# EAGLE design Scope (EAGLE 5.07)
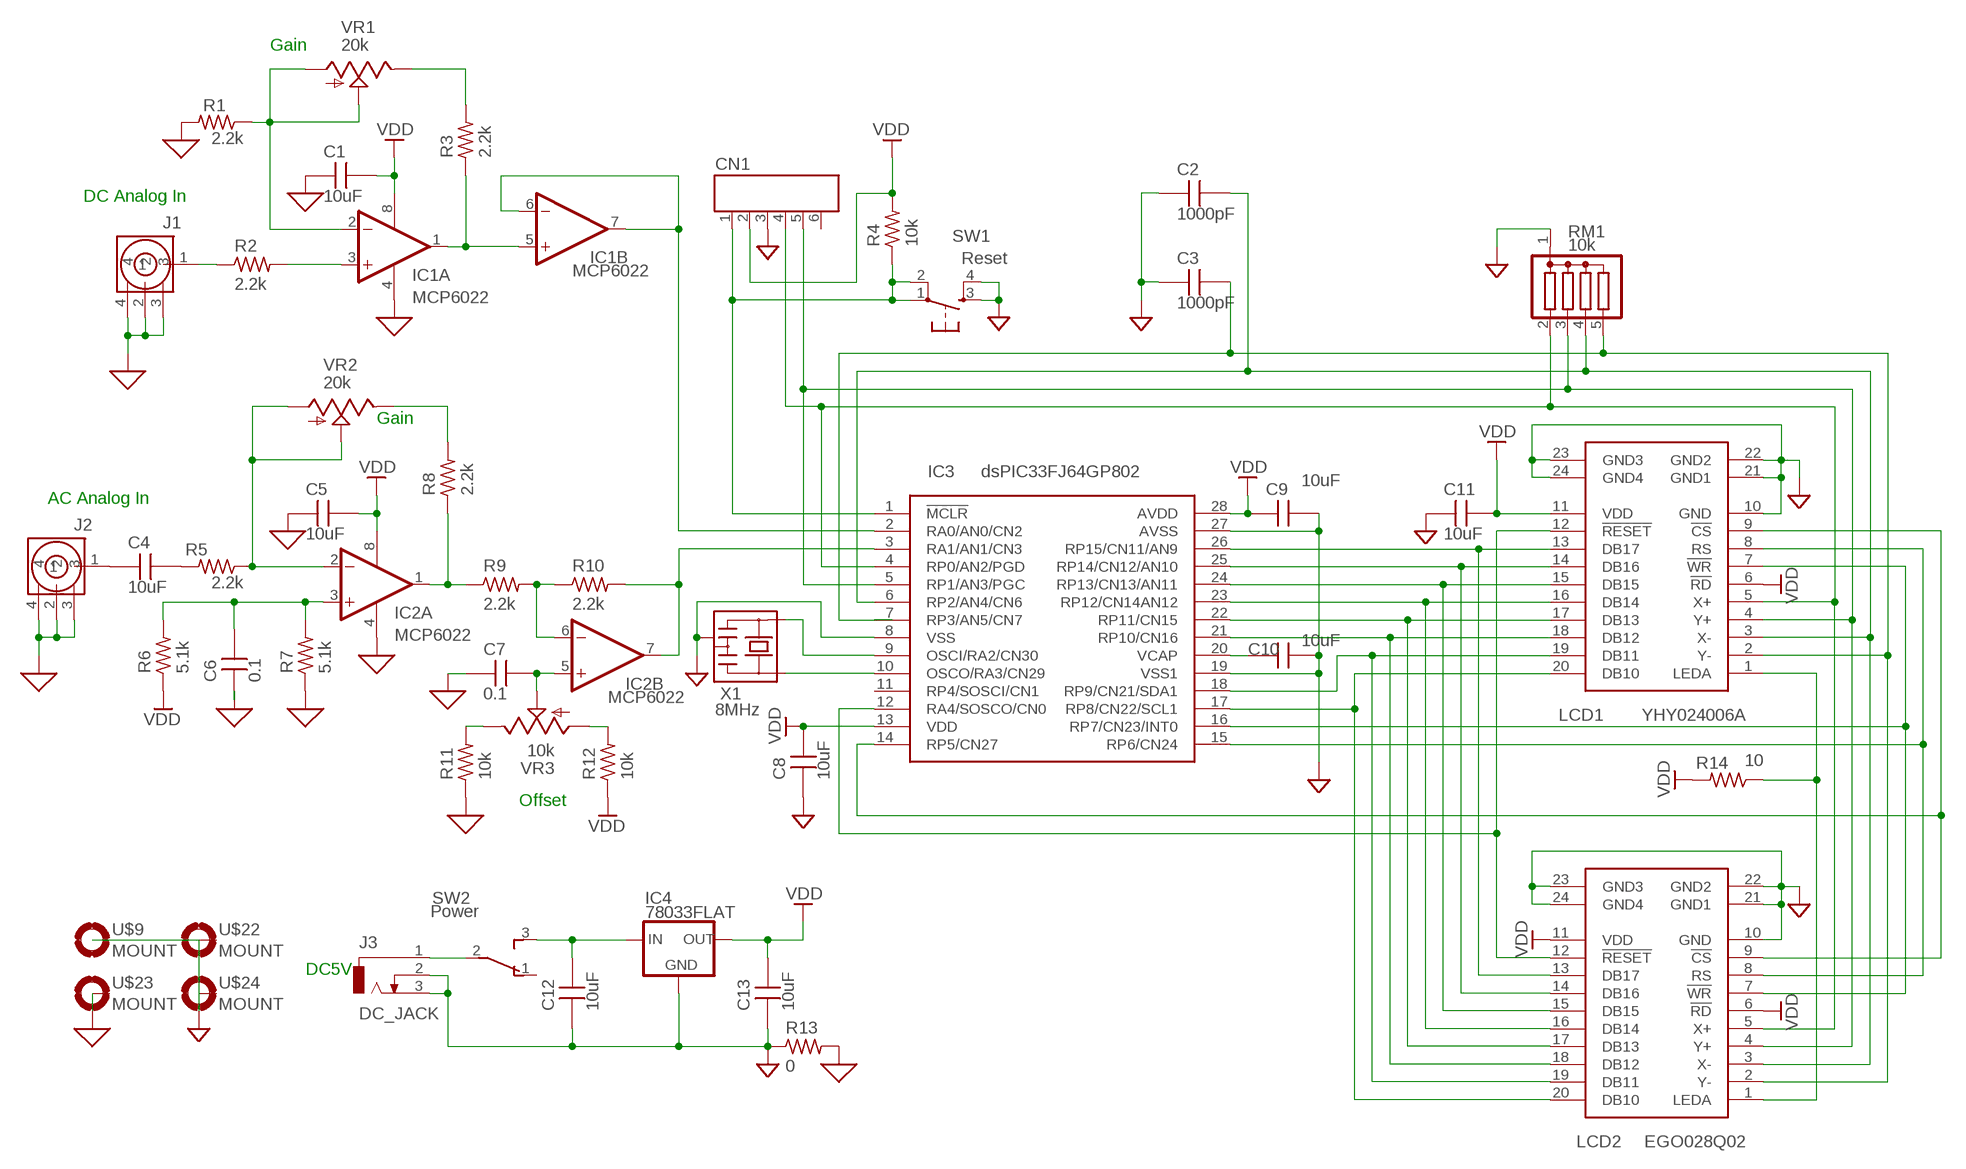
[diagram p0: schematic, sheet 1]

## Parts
C1  10uF  CAPSM3216  [C3216]
C2  1000pF  CAPDIP_2  [CAP_DIP_2]
C3  1000pF  CAPDIP_2  [CAP_DIP_2]
C4  10uF  CAPSM3216  [C3216]
C5  10uF  CAPSM3216  [C3216]
C6  0.1  CAPDIP_2  [CAP_DIP_2]
C7  0.1  CAPDIP_2  [CAP_DIP_2]
C8  10uF  CAPSM3216  [C3216]
C9  10uF  CAPSM3216  [C3216]
C10  10uF  CAPSM3216  [C3216]
C11  10uF  CAPSM3216  [C3216]
C12  10uF  CAPSM3225  [C3225]
C13  10uF  CAPSM3225  [C3225]
CN1  CON_6P  [CON_HRS_DIP_6]
IC1  MCP6022  LM358N  [DIL08]
IC2  MCP6022  LM358N  [DIL08]
IC3  dsPIC33FJ64GP802  DSPIC33FJ64GP802  [DIL28-3]
IC4  78033FLAT  7803FLAT  [TO252]
J1  RCA_JACK  [RCA_JACK]
J2  RCA_JACK  [RCA_JACK]
J3  DC_JACK  [DCJ0202]
LCD1  YHY024006A  LCD_YHY024006ABRD  [LCD_YHY024006ABRD]
LCD2  EGO028Q02  LCD_EGO028Q02BRD  [LCD_EGO028Q02BRD]
R1  2.2k  R0.125W_2P  [R_0.125W_2]
R2  2.2k  R0.125W_2P  [R_0.125W_2]
R3  2.2k  R0.125W_2P  [R_0.125W_2]
R4  10k  R0.125W_2P  [R_0.125W_2]
R5  2.2k  R0.125W_2P  [R_0.125W_2]
R6  5.1k  R0.125W_2P  [R_0.125W_2]
R7  5.1k  R0.125W_2P  [R_0.125W_2]
R8  2.2k  R0.125W_2P  [R_0.125W_2]
R9  2.2k  R0.125W_2P  [R_0.125W_2]
R10  2.2k  R0.125W_2P  [R_0.125W_2]
R11  10k  R0.125W_2P  [R_0.125W_2]
R12  10k  R0.125W_2P  [R_0.125W_2]
R13  0  R0.125W_2P  [R_0.125W_2]
R14  10  R0.125W_2P  [R_0.125W_2]
RM1  10k  RM4  [SIL5]
SW1  Reset  TACT-SW  [B3F-10X]
SW2  Power  SLIDESW-3  [DS-3]
U$9  MOUNT  MOUNT-PAD2.1  [PAD-2.1]
U$22  MOUNT  MOUNT-PAD2.1  [PAD-2.1]
U$23  MOUNT  MOUNT-PAD2.1  [PAD-2.1]
U$24  MOUNT  MOUNT-PAD2.1  [PAD-2.1]
VR1  20k  POTSMALL  [POT_B25P]
VR2  20k  POTSMALL  [POT_B25P]
VR3  10k  POTSMALL  [POT_B25P]
X1  8MHz  CERALOCK  [CSTLS]

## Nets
AGND: C1.1 C5.1 C6.1 C7.1 IC1.4(P:V-) IC2.4(P:V-) J1.2 J1.3 J1.4 J2.2 J2.3 J2.4 R1.2 R7.1 R11.1 R13.2 U$23.B2,1(MOUNT)
GND: C2.1 C3.1 C8.1 C9.2 C10.2 C11.1 C12.1 C13.1 CN1.3 IC3.8(VSS) IC3.19(VSS1) IC3.27(AVSS) IC4.3(GND) J3.2 J3.3 LCD1.10(GND) LCD1.21(GND1) LCD1.22(GND2) LCD1.23(GND3) LCD1.24(GND4) LCD2.10(GND) LCD2.21(GND1) LCD2.22(GND2) LCD2.23(GND3) LCD2.24(GND4) R13.1 RM1.1 SW1.3(S) SW1.4(S1) U$9.B2,1(MOUNT) U$22.B2,1(MOUNT) U$24.B2,1(MOUNT) X1.2
N$1: IC3.26(RP15/CN11/AN9) LCD1.13(DB17) LCD2.13(DB17)
N$2: IC3.25(RP14/CN12/AN10) LCD1.14(DB16) LCD2.14(DB16)
N$3: IC3.24(RP13/CN13/AN11) LCD1.15(DB15) LCD2.15(DB15)
N$4: IC3.23(RP12/CN14AN12) LCD1.16(DB14) LCD2.16(DB14)
N$5: IC3.22(RP11/CN15) LCD1.17(DB13) LCD2.17(DB13)
N$6: IC3.21(RP10/CN16) LCD1.18(DB12) LCD2.18(DB12)
N$7: IC3.18(RP9/CN21/SDA1) LCD1.19(DB11) LCD2.19(DB11)
N$9: IC3.16(RP7/CN23/INT0) LCD1.7(!WR) LCD2.7(!WR)
N$10: C2.2 IC3.6(RP2/AN4/CN6) LCD1.3(X-) LCD2.3(X-) RM1.4
N$11: IC3.14(RP5/CN27) LCD1.9(!CS) LCD2.9(!CS)
N$12: IC3.15(RP6/CN24) LCD1.8(RS) LCD2.8(RS)
N$13: LCD1.1(LEDA) LCD2.1(LEDA) R14.1
N$14: CN1.1 IC3.1(!MCLR) R4.1 SW1.1(P) SW1.2(P1)
N$15: IC3.12(RA4/SOSCO/CN0) LCD1.12(!RESET) LCD2.12(!RESET)
N$16: IC1.3(A:+IN) R2.2
N$17: IC1.6(B:-IN) IC1.7(B:OUT) IC3.2(RA0/AN0/CN2)
N$18: J3.1 SW2.2(P)
N$19: J1.1 R2.1
N$21: IC1.2(A:-IN) R1.1 VR1.A VR1.S
N$22: IC1.1(A:OUT) IC1.5(B:+IN) R3.1
N$23: CN1.4 IC3.4(RP0/AN2/PGD) LCD1.5(X+) LCD2.5(X+) RM1.2
N$24: C10.1 IC3.20(VCAP)
N$25: IC3.9(OSCI/RA2/CN30) X1.3
N$26: C4.1 J2.1
N$27: C3.2 IC3.7(RP3/AN5/CN7) LCD1.2(Y-) LCD2.2(Y-) RM1.5
N$28: C4.2 R5.2
N$29: C12.2 IC4.1(IN) SW2.3(S)
N$30: IC3.17(RP8/CN22/SCL1) LCD1.20(DB10) LCD2.20(DB10)
N$31: R11.2 VR3.E
N$32: R3.2 VR1.E
N$33: R12.2 VR3.A
N$34: IC2.2(A:-IN) R5.1 VR2.A VR2.S
N$35: C6.2 IC2.3(A:+IN) R6.2 R7.2
N$36: IC2.1(A:OUT) R8.1 R9.1
N$37: IC2.6(B:-IN) R9.2 R10.1
N$38: C7.2 IC2.5(B:+IN) VR3.S
N$39: CN1.5 IC3.5(RP1/AN3/PGC) LCD1.4(Y+) LCD2.4(Y+) RM1.3
N$40: R8.2 VR2.E
N$43: IC2.7(B:OUT) IC3.3(RA1/AN1/CN3) R10.2
N$46: IC3.10(OSCO/RA3/CN29) X1.1
VDD: C1.2 C5.2 C8.2 C9.1 C11.2 C13.2 CN1.2 IC1.8(P:V+) IC2.8(P:V+) IC3.13(VDD) IC3.28(AVDD) IC4.2(OUT) LCD1.6(!RD) LCD1.11(VDD) LCD2.6(!RD) LCD2.11(VDD) R4.2 R6.1 R12.1 R14.2
Unconnected: CN1.6 IC3.11(RP4/SOSCI/CN1) SW2.1(O)

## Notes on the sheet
- Gain
- DC Analog In
- Gain
- AC Analog In
- Offset
- DC5V

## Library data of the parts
C1-C13 = MyLib:CAP: Non polar capacitor
CN1 = MyLib:CON_6P: 6P Molex Connector
IC1 IC2 = linear:LM358: OP AMP also LM158; LM258; LM2904 Source: http://cache.national.com/ds/LM/LM158.pdf
IC3 = microchip-dspic:DSPIC33FJ64GP802: dsPIC33 RAM16K CAN
IC4 = MyLib:78*
J1 J2 = MyLib:RCA_JACK
J3 = MyLib:DC_JACK: DC Jack with Switch
LCD1 = MyLib:LCD_YHY024006ABRD: 2.4" TFT Color LCD with Touch Screen Board
LCD2 = MyLib:LCD_EGO028Q02BRD: 2.8" Color LCD Board with Touch Sensor
R1-R14 = MyLib:R: General Resiter 1/8W 1/4W 1/2W V/H
RM1 = MyLib:RM4: 4 Element Register Array Module
SW1 = MyLib:TACT-SW: Tacticle Push Switch
SW2 = MyLib:SLIDESW-3: 3P Slide Switch
U$9 U$22-U$24 = MyLib:MOUNT-PAD: 2.1mm Mount Pad (Connectable to GND)
VR1-VR3 = MyLib:POT: Volume Trimmer Resister
X1 = MyLib:CERALOCK: Ceralock Oscillator

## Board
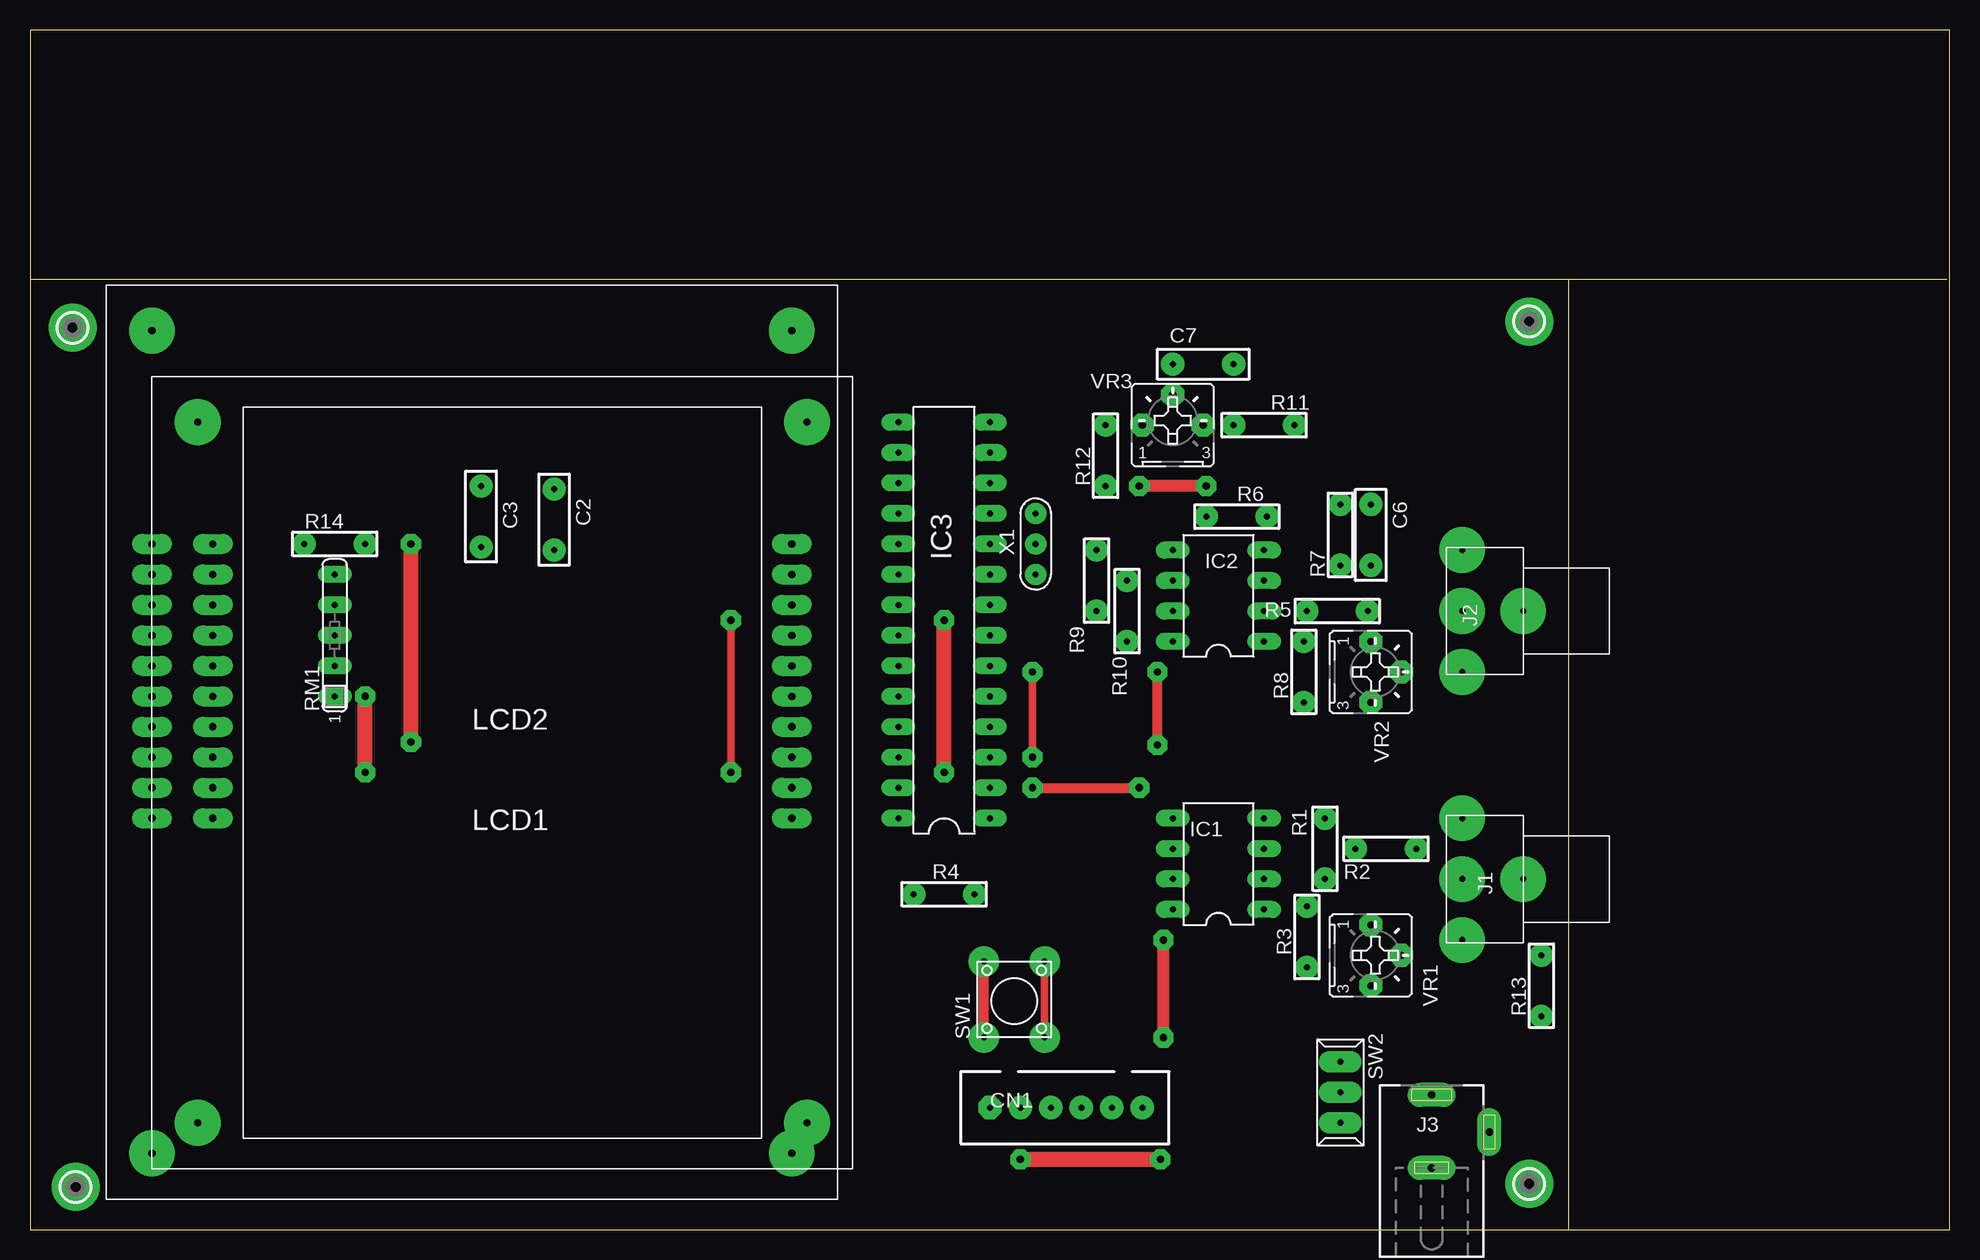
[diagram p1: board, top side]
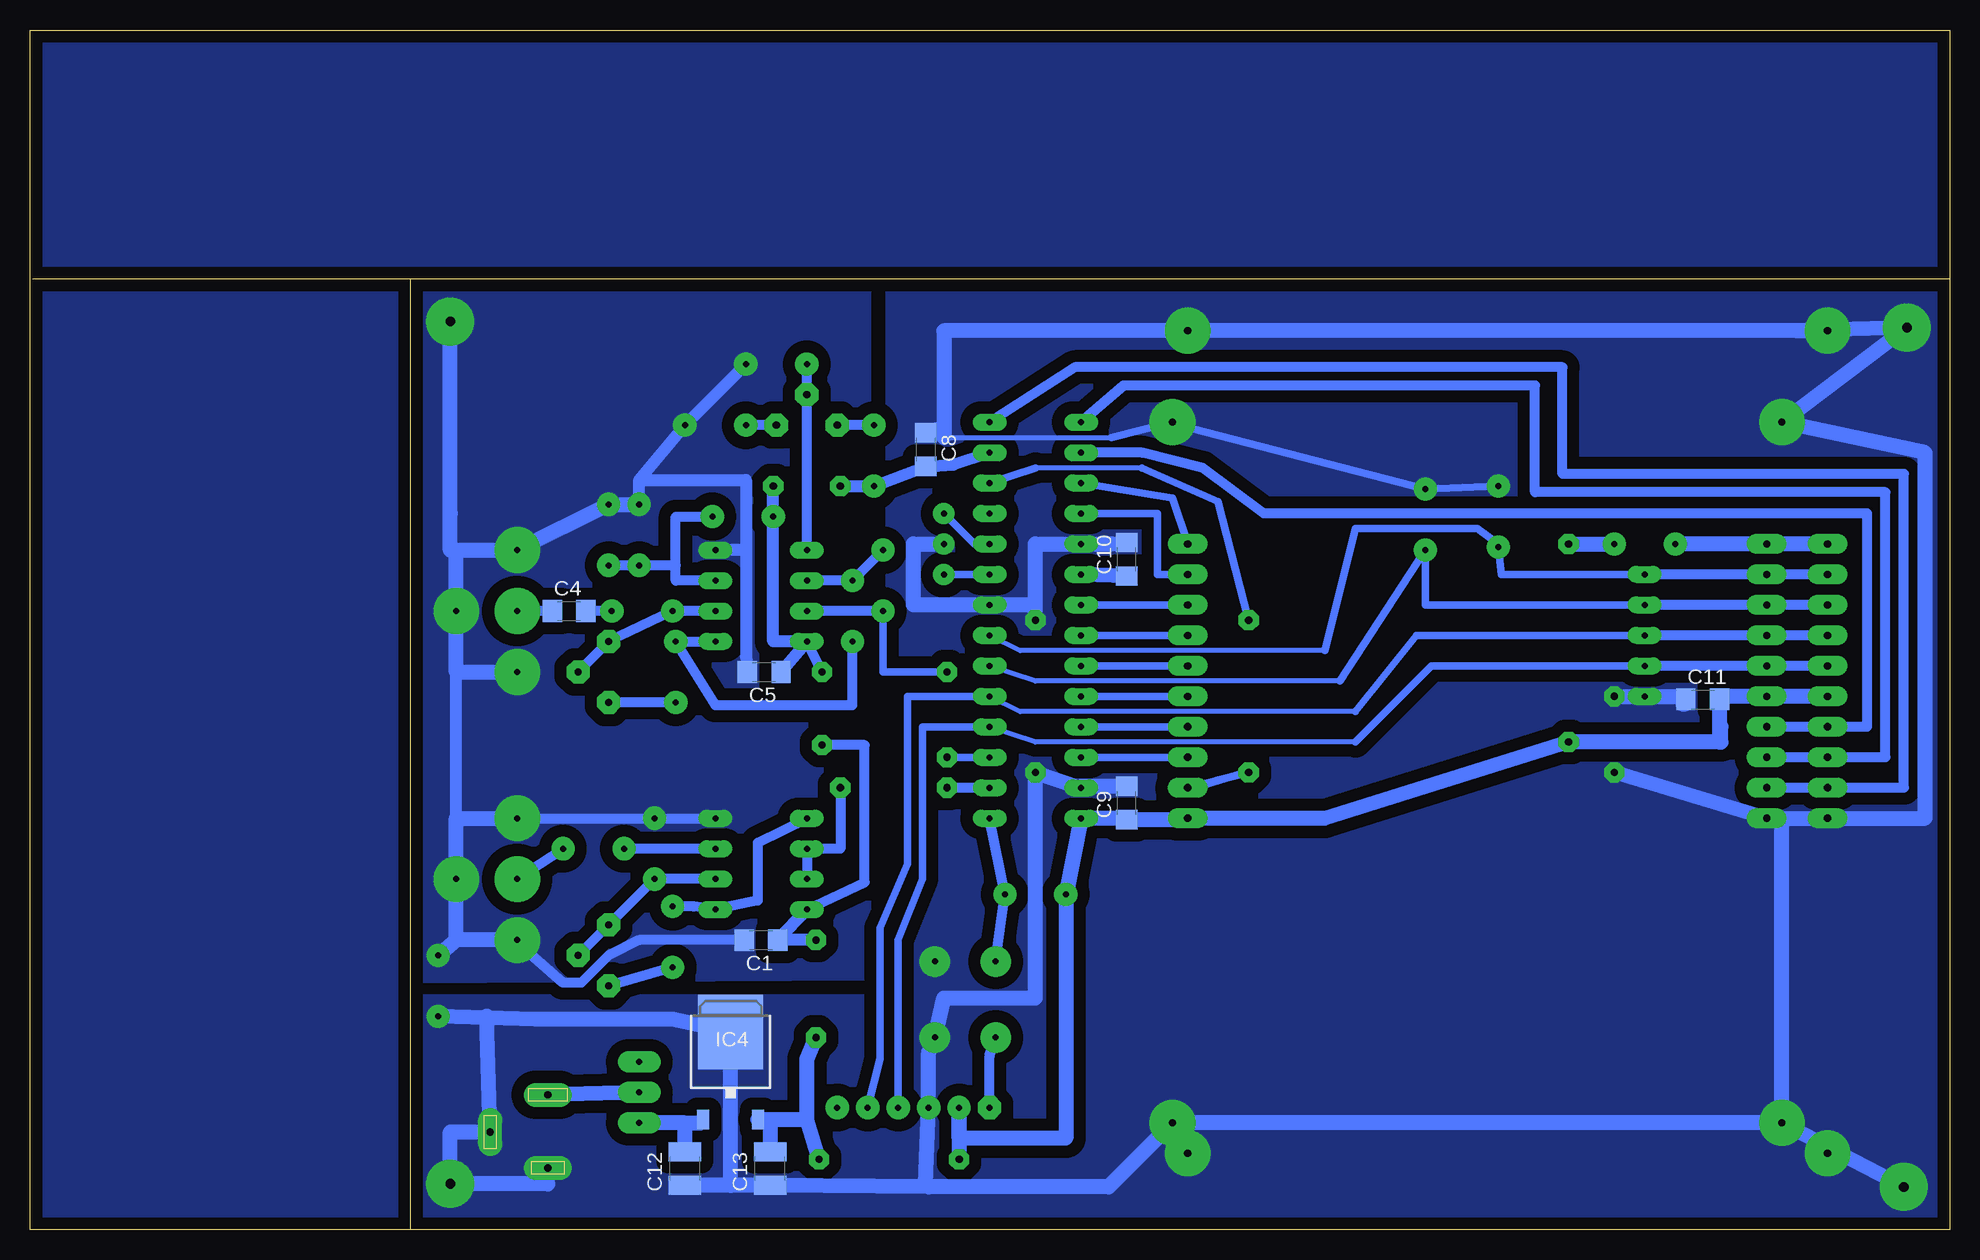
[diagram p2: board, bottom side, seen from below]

Size 160 x 100 mm. Coordinates in mm from the lower left corner, seen from the top.
Outline: 128.27,0 0,0 0,79.25
Outline: 0,79.25 0,100 160,100 160,0 128.27,0
Outline: 0,79.25 128.27,79.25
Outline: 128.27,79.25 159.77,79.25
Outline: 128.27,0 128.27,79.25
Copper layers (1*16): Top 0.035mm / dielectric 1.5mm / Bottom 0.035mm
Design rules "default": minimum track width 10mil, minimum drill 24mil, track to track 8mil, track to pad 8mil, pad to pad 8mil, via to via 8mil, smd to smd 8mil, copper to edge 40mil, drill to drill 8mil, minimum pad ring 10mil, minimum via ring 8mil, stop-mask expansion 4mil, vias tented up to drill 0mil, thermal gap 10mil

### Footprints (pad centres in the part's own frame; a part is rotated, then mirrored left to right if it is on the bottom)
C3216 = smd 1.6 x 1.8: 1 -1.4,0; 2 1.4,0
CAP_DIP_2 = drill 0.5 pad 1.93 round: 1 -2.54,0; 2 2.54,0
C3225 = smd 1.6 x 2.7: 1 -1.4,0; 2 1.4,0
CON_HRS_DIP_6 = drill 0.5 pad 1.93 octagon: 1 -6.35,0 | drill 0.5 pad 1.93 round: 2 -3.81,0; 3 -1.27,0; 4 1.27,0; 5 3.81,0; 6 6.35,0
DIL08 = drill 0.5 pad 1.422 long: 1 -3.81,-3.81; 2 -1.27,-3.81; 3 1.27,-3.81; 4 3.81,-3.81; 5 3.81,3.81; 6 1.27,3.81; 7 -1.27,3.81; 8 -3.81,3.81
DIL28-3 = drill 0.5 pad 1.422 long: 1 -16.51,-3.81; 2 -13.97,-3.81; 3 -11.43,-3.81; 4 -8.89,-3.81; 5 -6.35,-3.81; 6 -3.81,-3.81; 7 -1.27,-3.81; 8 1.27,-3.81; 9 3.81,-3.81; 10 6.35,-3.81; 11 8.89,-3.81; 12 11.43,-3.81; 13 13.97,-3.81; 14 16.51,-3.81; 15 16.51,3.81; 16 13.97,3.81; 17 11.43,3.81; 18 8.89,3.81; 19 6.35,3.81; 20 3.81,3.81; 21 1.27,3.81; 22 -1.27,3.81; 23 -3.81,3.81; 24 -6.35,3.81; 25 -8.89,3.81; 26 -11.43,3.81; 27 -13.97,3.81; 28 -16.51,3.81
TO252 = smd 1 x 1.6: 1 -2.28,-4.8; 2 2.28,-4.8 | smd 5.4 x 6.2: 3 0,2.5
RCA_JACK = drill 0.5 pad 3.81 round: 1 0,5.08; 2 0,0; 3 -5.08,5.08; 4 5.08,5.08
DCJ0202 = drill 0.6 pad 2 long: 1 0,6.148; 2 4.8,3.048; 3 0,0.048
LCD_YHY024006ABRD = drill 0.6 pad 1.676 long: 1 5.08,52.07; 2 5.08,49.53; 3 5.08,46.99; 4 5.08,44.45; 5 5.08,41.91; 6 5.08,39.37; 7 5.08,36.83; 8 5.08,34.29; 9 5.08,31.75; 10 5.08,29.21; 11 53.34,29.21; 12 53.34,31.75; 13 53.34,34.29; 14 53.34,36.83; 15 53.34,39.37; 16 53.34,41.91; 17 53.34,44.45; 18 53.34,46.99; 19 53.34,49.53; 20 53.34,52.07 | drill 0.6 pad 3.81 round: 21 3.81,62.23; 22 3.81,3.81; 23 54.61,3.81; 24 54.61,62.23
LCD_EGO028Q02BRD = drill 0.6 pad 1.676 long: 1 -25.4,17.78; 2 -25.4,15.24; 3 -25.4,12.7; 4 -25.4,10.16; 5 -25.4,7.62; 6 -25.4,5.08; 7 -25.4,2.54; 8 -25.4,0; 9 -25.4,-2.54; 10 -25.4,-5.08; 11 27.94,-5.08; 12 27.94,-2.54; 13 27.94,0; 14 27.94,2.54; 15 27.94,5.08; 16 27.94,7.62; 17 27.94,10.16; 18 27.94,12.7; 19 27.94,15.24; 20 27.94,17.78 | drill 0.6 pad 3.81 round: 21 -25.4,-33.02; 22 27.94,-33.02; 23 27.94,35.56; 24 -25.4,35.56
R_0.125W_2 = drill 0.5 pad 1.93 round: 1 -2.54,0; 2 2.54,0
SIL5 = drill 0.5 pad 1.422 long: 1 -5.08,0; 2 -2.54,0; 3 0,0; 4 2.54,0; 5 5.08,0
B3F-10X = drill 0.5 pad 2.54 round: 1 -1.27,2.54; 2 5.08,2.54; 3 -1.27,-2.54; 4 5.08,-2.54
DS-3 = drill 0.5 pad 1.778 long: 1 0,-2.54; 2 0,0; 3 0,2.54
PAD-2.1 = drill 0.8 pad 4 round: B2,1 0,0
POT_B25P = drill 0.6 pad 1.93 octagon: A -2.54,0; E 2.54,0; S 0,2.54
CSTLS = drill 0.5 pad 1.778 round: 1 -2.54,0; 2 0,0; 3 2.54,0

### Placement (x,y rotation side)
C1  99.06,24.13 0 bottom
C2  43.69,59.18 270 top
C3  37.59,59.44 270 top
C4  115.06,51.56 0 bottom
C5  98.81,46.48 0 bottom
C6  111.76,57.91 270 top
C7  97.79,72.14 180 top
C8  85.34,65.02 270 bottom
C9  68.58,35.56 90 bottom
C10  68.58,55.88 90 bottom
C11  20.57,44.2 0 bottom
C12  105.41,5.08 90 bottom
C13  98.3,5.08 90 bottom
CN1  86.36,10.16 0 top
IC1  99.06,30.48 90 top
IC2  99.06,52.83 90 top
IC3  76.2,50.8 90 top
IC4  101.6,13.97 0 bottom
J1  124.46,29.21 90 top
J2  124.46,51.56 90 top
J3  116.84,5.08 0 top
LCD1  10.16,5.08 0 top
LCD2  35.56,39.37 0 top
R1  107.95,31.75 90 top
R2  113.03,31.75 180 top
R3  106.43,24.38 270 top
R4  76.2,27.94 180 top
R5  108.97,51.56 0 top
R6  100.58,59.44 0 top
R7  109.22,57.91 270 top
R8  106.17,46.48 270 top
R9  91.44,51.56 90 top
R10  88.9,54.1 270 top
R11  102.87,67.06 180 top
R12  89.66,64.52 90 top
R13  125.98,20.32 90 top
R14  25.4,57.15 0 top
RM1  25.4,49.53 90 top
SW1  82.04,17.27 90 top
SW2  109.22,11.43 180 top
U$9  124.97,3.81 0 top
U$22  3.81,3.56 0 top
U$23  124.97,75.69 0 top
U$24  3.56,75.18 0 top
VR1  111.76,22.86 270 top
VR2  111.76,46.48 270 top
VR3  95.25,67.06 0 top
X1  83.82,57.15 270 top

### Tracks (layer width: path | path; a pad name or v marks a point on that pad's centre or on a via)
AGND
  Bottom 0.813: IC1.4 R1.2 J1.4 | 119.63,24.13 115.57,20.57 114.05,20.57 111.76,22.86 109.22,24.13 C1.1
  Bottom 1.016: 100.33,56.64 IC2.4 | 100.33,56.64 100.33,47.75 C5.1 | 124.46,34.29 124.46,46.48 | 100.33,56.64 100.33,62.48 109.22,62.48 | R7.1 109.22,62.48 | C7.1 R11.1 109.22,62.48
  Bottom 1.27: R7.1 C6.1 J2.4 124.46,56.64 | 124.46,56.64 J2.2 124.46,46.48 J2.3 | J1.4 124.46,34.29 J1.2 124.46,24.13 | 124.46,24.13 119.63,24.13 J1.3 | 124.46,56.64 124.97,56.64 124.97,59.69 U$23.B2,1 | 124.46,24.13 R13.2
  pour Bottom (isolate 1.016, no thermals): 128.27,79.5 90.17,79.5 90.17,21.08 128.27,20.83
GND  (via drill 0.6 pad 1.68)
  Top 0.61: SW1.3 SW1.4
  Top 1.27: v27.94,38.1 v27.94,44.45 | v76.2,38.1 v76.2,50.8
  Bottom 0.406: 83.82,66.04 69.85,66.04
  Bottom 0.61: 69.85,66.04 LCD1.24 64.26,67.06 C2.1 C3.1
  Bottom 1.016: 22.35,44.45 22.35,43.69 21.97,43.69 C11.1 | IC3.27 72.39,36.96
  Bottom 1.27: X1.2 86.36,57.15 86.36,52.07 IC3.8 76.2,52.07 | C10.2 69.85,57.15 IC3.19 76.2,57.15 76.2,52.07 | IC3.27 v76.2,38.1 76.2,19.3 83.82,19.3 SW1.3 85.09,14.73 CN1.3 85.34,3.81 85.09,3.56 | v27.94,44.45 RM1.1 22.35,44.45 | LCD1.10 v27.94,38.1 | LCD1.22 13.97,34.29 LCD1.10 | U$22.B2,1 10.04,6.83 | 10.04,6.83 LCD1.22 | LCD1.22 LCD1.23 65.15,8.51 | 65.15,8.51 70.1,3.56 85.09,3.56 | 85.09,3.56 C13.1 101.6,3.68 | 101.6,3.68 C12.1 | 101.6,3.68 IC4.3 106.43,17.53 117.86,17.53 R13.1 | v76.2,50.8 76.2,52.07 | J3.3 116.84,3.81 U$9.B2,1 124.97,8.13 J3.2 121.92,17.78 | 83.82,66.8 83.82,74.93 LCD2.23 12.7,74.93 | 83.82,66.8 83.82,66.04 | 12.7,74.93 U$24.B2,1 LCD1.21 2.03,64.77 2.03,34.29 LCD2.10 LCD1.10 | 12.7,74.93 LCD2.24 | 10.04,6.83 LCD2.21 | 65.15,8.51 LCD2.22 | 72.39,36.96 C9.2 | 83.82,66.8 C8.1
  pour Bottom (isolate 1.016, no thermals): -0.25,79.5 88.39,79.5 88.39,19.3 128.78,19.3 128.78,-0.25 -0.25,-0.25
N$1
  Bottom 0.61: LCD2.13 IC3.26
N$2
  Bottom 0.61: LCD2.14 63.75,41.91 IC3.25
N$3
  Bottom 0.61: LCD2.15 64.01,44.45 IC3.24
N$4
  Bottom 0.61: LCD2.16 IC3.23
N$5
  Bottom 0.61: LCD2.17 IC3.22
N$6
  Bottom 0.61: LCD2.18 IC3.21
N$7
  Bottom 0.61: LCD2.19 66.04,54.61 66.04,59.69 IC3.18
N$8
  pour Bottom (isolate 1.016, no thermals): 0,100.33 160.02,100.33 160.02,78.74 0,78.74
N$9
  Bottom 0.813: IC3.16 67.31,64.77 62.23,63.5 57.15,59.69 6.86,59.69 6.86,41.91 LCD2.7 LCD1.7
N$10
  Bottom 0.406: 50.8,45.72 76.2,45.72 IC3.6
  Bottom 0.61: RM1.4 43.69,52.07 C2.2 50.8,45.72
  Bottom 0.813: RM1.4 LCD1.3 LCD2.3
N$11
  Bottom 0.813: IC3.14 72.9,71.88 32.26,71.88 32.26,62.99 3.81,62.99 3.81,36.83 LCD2.9 LCD1.9
N$12
  Bottom 0.813: IC3.15 68.83,70.36 34.54,70.36 34.54,61.47 5.33,61.47 5.33,39.37 LCD2.8 LCD1.8
N$13
  Bottom 1.27: R14.1 LCD1.1 LCD2.1
N$14
  Top 0.813: SW1.1 SW1.2
  Bottom 0.813: IC3.1 R4.1 SW1.2 | CN1.1 80.01,14.48 SW1.1
N$15  (via drill 0.6 pad 1.68)
  Top 0.61: v58.42,38.1 v58.42,50.8
  Bottom 0.406: 67.31,63.5 76.2,63.5 | LCD2.12 60.96,37.59 58.93,38.1 58.67,38.1
  Bottom 0.61: v58.42,38.1 LCD2.12 | v58.42,50.8 60.96,60.71 67.31,63.5 | 76.2,63.5 IC3.12 | 58.67,38.1 62.99,36.83
N$16
  Bottom 0.813: IC1.3 R2.2
N$17  (via drill 0.6 pad 1.68)
  Top 0.813: v83.57,36.83 v92.46,36.83
  Bottom 0.813: IC1.7 IC1.6 92.46,31.75 v92.46,36.83 | IC3.2 v83.57,36.83
N$18
  Bottom 1.27: SW2.2 J3.1
N$19
  Bottom 0.813: R2.1 J1.1
N$20
  pour Bottom (isolate 1.016, no thermals): 160.02,0 128.27,0 128.27,78.74 160.02,78.74
N$21
  Bottom 0.813: VR1.S VR1.A R1.1 IC1.2
N$22
  Bottom 0.813: R3.1 104.65,26.92 IC1.1 99.31,27.43 99.31,32.26 IC1.5
N$23
  Bottom 0.406: 49.53,40.64 76.2,40.64 IC3.4
  Bottom 0.61: IC3.4 85.6,41.91 85.6,29.21 87.63,24.13 CN1.4 | RM1.2 43.18,46.99 49.53,40.64
  Bottom 0.813: RM1.2 LCD1.5 LCD2.5
N$24
  Bottom 1.27: C10.1 IC3.20
N$25
  Bottom 0.61: IC3.9 X1.3
N$26
  Bottom 0.813: C4.1 J2.1
N$27
  Bottom 0.406: 52.07,48.26 77.47,48.26 IC3.7
  Bottom 0.61: RM1.5 37.34,54.61 C3.2 37.59,57.15 39.37,58.42 49.53,58.42 52.07,48.26
  Bottom 0.813: RM1.5 LCD1.2 LCD2.2
N$28
  Bottom 0.813: R5.2 C4.2
N$29
  Bottom 0.61: 104.14,8.89 IC4.1
  Bottom 1.27: 105.41,8.89 104.14,8.89 | C12.2 105.41,8.89 | 105.41,8.89 SW2.3
N$30
  Bottom 0.61: LCD2.20 64.77,60.96 IC3.17
N$31
  Bottom 0.813: VR3.E R11.2
N$32
  Bottom 0.813: R3.2 VR1.E
N$33
  Bottom 0.813: R12.2 VR3.A
N$34
  Bottom 0.813: IC2.2 R5.1 VR2.A VR2.S
N$35
  Bottom 0.813: IC2.3 106.17,54.1 106.17,55.37 | R6.2 106.17,59.44 106.17,55.37 | 106.17,55.37 R7.2 C6.2
N$36
  Bottom 0.813: IC2.1 R8.1 102.87,43.69 91.44,43.69 R9.1
N$37
  Bottom 0.813: R10.1 R9.2 IC2.6
N$38
  Bottom 0.813: C7.2 VR3.S IC2.5
N$39
  Bottom 0.406: 49.53,43.18 77.47,43.18 IC3.5
  Bottom 0.61: IC3.5 86.87,44.45 86.87,30.48 89.15,25.15 89.15,14.22 CN1.5 | RM1.3 44.45,49.53 49.53,43.18
  Bottom 0.813: RM1.3 LCD1.4 LCD2.4
N$40
  Bottom 0.813: R8.2 VR2.E
N$43  (via drill 0.6 pad 1.68)
  Top 0.61: v83.57,39.37 v83.57,46.48
  Bottom 0.61: IC3.3 v83.57,39.37 | v83.57,46.48 88.9,46.48 R10.2
  Bottom 0.813: R10.2 IC2.7
N$46
  Bottom 0.61: IC3.10 81.28,57.15 X1.1
VDD  (via drill 0.6 pad 1.68)
  Top 0.813: v93.98,40.39 v93.98,46.48
  Top 1.016: v94.49,16 v94.49,24.13 | v98.04,61.98 v92.46,61.98
  Top 1.27: v31.75,40.64 v31.75,57.15 | v82.55,5.84 v94.23,5.84
  Bottom 0.813: IC1.8 90.42,28.96 90.42,40.39 v93.98,40.39 | v93.98,46.48 IC2.8
  Bottom 1.016: IC1.8 C1.2 v94.49,24.13 | C5.2 IC2.8 98.04,49.02 R6.1 v98.04,61.98 | v92.46,61.98 R12.1 C8.2 83.06,63.75 IC3.13 | 19.17,40.64 19.05,40.64 | 19.17,44.45 C11.2 | C9.1 68.58,34.29 | LCD2.11 63.5,34.16
  Bottom 1.27: LCD2.11 52.07,34.29 v31.75,40.64 19.05,40.64 19.05,41.91 | v31.75,57.15 R14.2 | 98.3,9.14 IC4.2 | 98.3,9.14 C13.2 | v82.55,5.84 CN1.2 82.55,7.62 73.66,7.62 R4.2 IC3.28 68.58,34.29 | 95.25,9.14 98.3,9.14 | v94.23,5.84 95.25,9.14 | 95.25,9.14 95.25,14.22 v94.49,16 | LCD2.6 LCD1.6 19.17,44.45 | C11.2 19.17,40.64 | 63.5,34.16 C9.1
